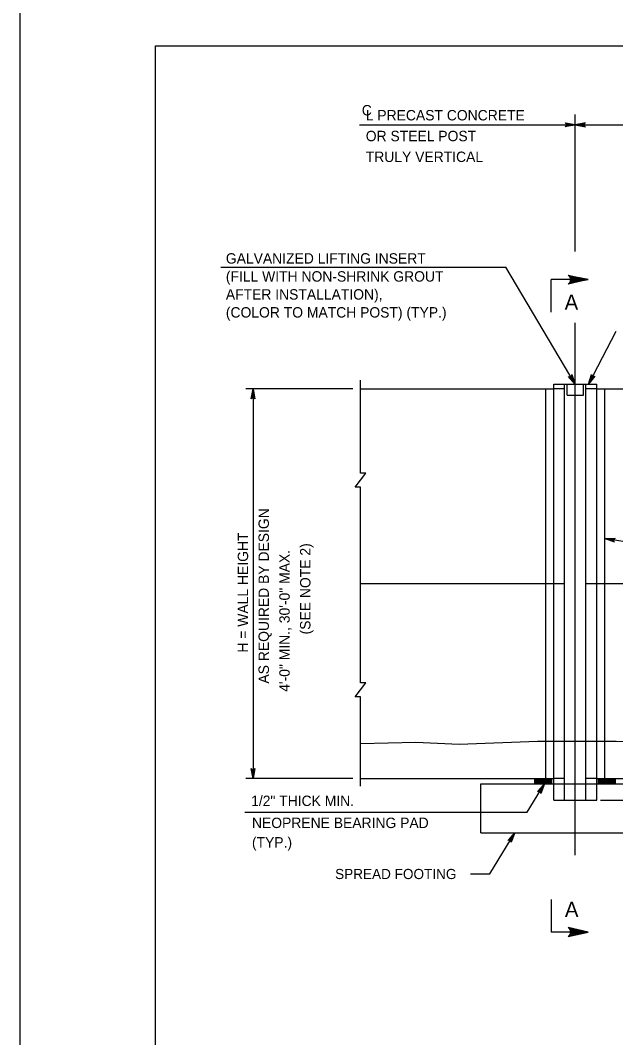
# Model space of a CAD drawing. Extents: x 3761 to 5458, y -616 to 1166.
# Drawn here: x 3761.3 to 3937.4, y 263.6 to 564.2 of the extents above; entities that cross this region are included whole.
import ezdxf

# ---------------------------------------------------------------- set-up
doc = ezdxf.new("R2010")
doc.units = 0
for name, color, linetype in [('1', 7, 'Continuous'), ('2', 7, 'Continuous'), ('PLT-BNDY', 7, 'Continuous')]:
    doc.layers.add(name, color=color, linetype=linetype)

msp = doc.modelspace()

# ---------------------------------------------------------------- linework, layer by layer
at = {"layer": '1'}
for p, q in [((3925.47, 495.93), (3925.47, 536.33)), ((3861.66, 533.3), (4143.42, 533.3)), ((3820.64, 491.27), (3904.95, 491.27)), ((3925.47, 456.66), (3904.95, 491.27)), ((3918.31, 478), (3918.31, 487.65)), ((3929.31, 487.65), (3918.31, 487.65)), ((3925.47, 317.53), (3925.47, 474.78)), ((3937.42, 472.24), (3929.42, 456.66)), ((3861.98, 430.38), (3861.98, 457.89)), ((3859.69, 455.3), (3828, 455.3)), ((3830.16, 455.3), (3830.16, 340.1)), ((3861.98, 455.3), (3919.12, 455.3)), ((3916.72, 340.1), (3916.72, 455.3)), ((3919.12, 338.52), (3919.12, 456.66)), ((3919.12, 456.66), (3931.81, 456.66)), ((3922.29, 455.3), (3919.12, 455.3)), ((3922.29, 333.72), (3922.29, 456.66)), ((3923.07, 453.46), (3923.07, 456.66)), ((3927.87, 453.46), (3927.87, 456.66)), ((3928.64, 333.72), (3928.64, 456.66)), ((3931.81, 455.3), (3928.64, 455.3)), ((3931.81, 338.52), (3931.81, 456.66)), ((3931.81, 455.3), (4072.72, 455.3)), ((3934.21, 340.1), (3934.21, 455.3)), ((3923.07, 453.46), (3927.87, 453.46)), ((3861.98, 368.44), (3861.98, 426.21)), ((4070.32, 388.95), (3934.21, 411.04)), ((3922.29, 397.7), (3861.98, 397.7)), ((4075.89, 397.7), (3928.64, 397.7)), ((3861.98, 337.85), (3861.98, 364.26)), ((3859.69, 340.1), (3828, 340.1)), ((3861.98, 340.1), (3919.12, 340.1)), ((3913.56, 338.52), (3913.56, 340.1)), ((3913.56, 339.92), (3918.55, 339.92)), ((3918.55, 338.52), (3918.55, 340.1)), ((3922.29, 340.1), (3919.12, 340.1)), ((3931.81, 340.1), (3928.64, 340.1)), ((3931.81, 340.1), (3944.01, 340.1)), ((3932.37, 338.52), (3932.37, 340.1)), ((3932.37, 339.92), (3937.37, 339.92)), ((3937.37, 338.52), (3937.37, 340.1)), ((3897.57, 338.52), (3953.36, 338.52)), ((3897.57, 324.12), (3897.57, 338.52)), ((3911.28, 330.21), (3916.34, 338.52)), ((3913.56, 339.72), (3918.55, 339.72)), ((3913.56, 339.52), (3918.55, 339.52)), ((3913.56, 339.32), (3918.55, 339.32)), ((3913.56, 339.12), (3918.55, 339.12)), ((3913.56, 338.92), (3918.55, 338.92)), ((3913.56, 338.72), (3918.55, 338.72)), ((3913.56, 338.52), (3918.55, 338.52)), ((3919.12, 333.72), (3919.12, 338.52)), ((3931.81, 333.72), (3931.81, 338.52)), ((3932.37, 339.72), (3937.37, 339.72)), ((3932.37, 339.52), (3937.37, 339.52)), ((3932.37, 339.32), (3937.37, 339.32)), ((3932.37, 339.12), (3937.37, 339.12)), ((3932.37, 338.92), (3937.37, 338.92)), ((3932.37, 338.72), (3937.37, 338.72)), ((3919.12, 333.72), (3931.81, 333.72)), ((3932.96, 333.72), (3947.1, 333.72)), ((3827.77, 330.21), (3911.28, 330.21)), ((3897.57, 324.12), (3953.36, 324.12)), ((3900.19, 311.96), (3907.59, 324.12)), ((3894.52, 311.96), (3900.19, 311.96)), ((3918.31, 304.39), (3918.31, 294.74)), ((3929.31, 294.74), (3918.31, 294.74))]:
    msp.add_line(p, q, dxfattribs=at)
for points in [[(3925.47, 533.3), (3922.48, 532.74), (3922.6, 532.82), (3922.71, 532.9), (3922.77, 533), (3922.83, 533.1), (3922.85, 533.2), (3922.87, 533.3), (3922.85, 533.4), (3922.83, 533.5), (3922.77, 533.6), (3922.71, 533.7), (3922.6, 533.78), (3922.48, 533.86), (3925.47, 533.3), (3922.6, 533.78), (3922.71, 533.7), (3925.47, 533.3), (3922.77, 533.6), (3922.83, 533.5), (3925.47, 533.3), (3922.85, 533.4), (3922.87, 533.3), (3925.47, 533.3), (3922.85, 533.2), (3922.83, 533.1), (3925.47, 533.3), (3922.77, 533), (3922.71, 532.9), (3925.47, 533.3), (3922.6, 532.82)], [(3925.47, 533.3), (3928.45, 532.74), (3928.33, 532.82), (3928.22, 532.9), (3928.16, 533), (3928.1, 533.1), (3928.08, 533.2), (3928.07, 533.3), (3928.08, 533.4), (3928.1, 533.5), (3928.16, 533.6), (3928.22, 533.7), (3928.33, 533.78), (3928.45, 533.86), (3925.47, 533.3), (3928.33, 533.78), (3928.22, 533.7), (3925.47, 533.3), (3928.16, 533.6), (3928.1, 533.5), (3925.47, 533.3), (3928.08, 533.4), (3928.07, 533.3), (3925.47, 533.3), (3928.08, 533.2), (3928.1, 533.1), (3925.47, 533.3), (3928.16, 533), (3928.22, 532.9), (3925.47, 533.3), (3928.33, 532.82)], [(3929.31, 487.65), (3923.35, 486.23), (3923.58, 486.43), (3923.81, 486.62), (3923.93, 486.86), (3924.04, 487.1), (3924.08, 487.34), (3924.11, 487.58), (3924.07, 487.82), (3924.03, 488.06), (3923.91, 488.3), (3923.79, 488.54), (3923.56, 488.73), (3923.33, 488.92), (3929.31, 487.65), (3923.56, 488.73), (3923.79, 488.54), (3929.31, 487.65), (3923.91, 488.3), (3924.03, 488.06), (3929.31, 487.65), (3924.07, 487.82), (3924.11, 487.58), (3929.31, 487.65), (3924.08, 487.34), (3924.04, 487.1), (3929.31, 487.65), (3923.93, 486.86), (3923.81, 486.62), (3929.31, 487.65), (3923.58, 486.43)], [(3925.47, 456.66), (3923.46, 458.94), (3923.72, 458.82), (3923.95, 458.82), (3924.14, 458.89), (3924.29, 459.02), (3924.41, 459.23), (3924.43, 459.51), (3925.47, 456.66), (3924.41, 459.23), (3924.29, 459.02), (3925.47, 456.66), (3924.14, 458.89), (3923.95, 458.82), (3925.47, 456.66), (3923.72, 458.82)], [(3929.42, 456.66), (3930.28, 459.56), (3930.3, 459.43), (3930.32, 459.29), (3930.38, 459.19), (3930.44, 459.09), (3930.53, 459.03), (3930.61, 458.97), (3930.7, 458.94), (3930.8, 458.91), (3930.92, 458.92), (3931.03, 458.92), (3931.16, 458.99), (3931.28, 459.05), (3929.42, 456.66), (3931.16, 458.99), (3931.03, 458.92), (3929.42, 456.66), (3930.92, 458.92), (3930.8, 458.91), (3929.42, 456.66), (3930.7, 458.94), (3930.61, 458.97), (3929.42, 456.66), (3930.53, 459.03), (3930.44, 459.09), (3929.42, 456.66), (3930.38, 459.19), (3930.32, 459.29), (3929.42, 456.66), (3930.3, 459.43)], [(3830.16, 455.3), (3830.72, 452.32), (3830.64, 452.44), (3830.56, 452.55), (3830.46, 452.61), (3830.36, 452.67), (3830.26, 452.69), (3830.16, 452.7), (3830.06, 452.69), (3829.96, 452.67), (3829.86, 452.61), (3829.76, 452.55), (3829.68, 452.44), (3829.6, 452.32), (3830.16, 455.3), (3829.68, 452.44), (3829.76, 452.55), (3830.16, 455.3), (3829.86, 452.61), (3829.96, 452.67), (3830.16, 455.3), (3830.06, 452.69), (3830.16, 452.7), (3830.16, 455.3), (3830.26, 452.69), (3830.36, 452.67), (3830.16, 455.3), (3830.46, 452.61), (3830.56, 452.55), (3830.16, 455.3), (3830.64, 452.44)], [(3861.98, 426.21), (3860.39, 426.21), (3863.56, 430.38), (3861.98, 430.38)], [(3934.21, 411.04), (3937.25, 411.11), (3936.99, 410.99), (3936.85, 410.82), (3936.78, 410.62), (3936.78, 410.42), (3936.87, 410.2), (3937.07, 410.01), (3934.21, 411.04), (3936.87, 410.2), (3936.78, 410.42), (3934.21, 411.04), (3936.78, 410.62), (3936.85, 410.82), (3934.21, 411.04), (3936.99, 410.99)], [(3861.98, 364.26), (3860.39, 364.26), (3863.56, 368.44), (3861.98, 368.44)], [(3861.98, 350.45), (3878.35, 350.9), (3891.12, 350.32), (3914.31, 351.17), (3937.57, 351.17), (3961.32, 351.07), (3966.64, 351.17), (3982.01, 351.07), (3996.76, 351.17), (4011.56, 350.95), (4046.92, 351.17), (4066.47, 350.64), (4086.26, 348.09), (4094.49, 346.67), (4106.93, 345.35), (4120.71, 343.61), (4143.22, 341.33), (4160.6, 339.19), (4243, 332.75), (4279.86, 332.38)], [(3830.16, 340.1), (3829.6, 343.09), (3829.68, 342.97), (3829.76, 342.86), (3829.86, 342.8), (3829.96, 342.74), (3830.06, 342.72), (3830.16, 342.7), (3830.26, 342.72), (3830.36, 342.74), (3830.46, 342.8), (3830.56, 342.86), (3830.64, 342.97), (3830.72, 343.09), (3830.16, 340.1), (3830.64, 342.97), (3830.56, 342.86), (3830.16, 340.1), (3830.46, 342.8), (3830.36, 342.74), (3830.16, 340.1), (3830.26, 342.72), (3830.16, 342.7), (3830.16, 340.1), (3830.06, 342.72), (3829.96, 342.74), (3830.16, 340.1), (3829.86, 342.8), (3829.76, 342.86), (3830.16, 340.1), (3829.68, 342.97)], [(3916.34, 338.52), (3915.26, 335.68), (3915.25, 335.82), (3915.25, 335.96), (3915.19, 336.06), (3915.14, 336.16), (3915.06, 336.23), (3914.98, 336.3), (3914.89, 336.33), (3914.8, 336.37), (3914.68, 336.37), (3914.56, 336.37), (3914.44, 336.32), (3914.31, 336.26), (3916.34, 338.52), (3914.44, 336.32), (3914.56, 336.37), (3916.34, 338.52), (3914.68, 336.37), (3914.8, 336.37), (3916.34, 338.52), (3914.89, 336.33), (3914.98, 336.3), (3916.34, 338.52), (3915.06, 336.23), (3915.14, 336.16), (3916.34, 338.52), (3915.19, 336.06), (3915.25, 335.96), (3916.34, 338.52), (3915.25, 335.82)], [(3907.59, 324.12), (3906.52, 321.28), (3906.51, 321.42), (3906.5, 321.56), (3906.45, 321.66), (3906.39, 321.76), (3906.32, 321.83), (3906.24, 321.9), (3906.15, 321.93), (3906.05, 321.97), (3905.94, 321.97), (3905.82, 321.97), (3905.69, 321.92), (3905.56, 321.86), (3907.59, 324.12), (3905.69, 321.92), (3905.82, 321.97), (3907.59, 324.12), (3905.94, 321.97), (3906.05, 321.97), (3907.59, 324.12), (3906.15, 321.93), (3906.24, 321.9), (3907.59, 324.12), (3906.32, 321.83), (3906.39, 321.76), (3907.59, 324.12), (3906.45, 321.66), (3906.5, 321.56), (3907.59, 324.12), (3906.51, 321.42)], [(3929.31, 294.74), (3923.35, 296.15), (3923.58, 295.96), (3923.81, 295.77), (3923.93, 295.53), (3924.04, 295.28), (3924.08, 295.04), (3924.11, 294.8), (3924.07, 294.56), (3924.03, 294.32), (3923.91, 294.09), (3923.79, 293.85), (3923.56, 293.66), (3923.33, 293.47), (3929.31, 294.74), (3923.56, 293.66), (3923.79, 293.85), (3929.31, 294.74), (3923.91, 294.09), (3924.03, 294.32), (3929.31, 294.74), (3924.07, 294.56), (3924.11, 294.8), (3929.31, 294.74), (3924.08, 295.04), (3924.04, 295.28), (3929.31, 294.74), (3923.93, 295.53), (3923.81, 295.77), (3929.31, 294.74), (3923.58, 295.96)]]:
    msp.add_lwpolyline(points, dxfattribs=at)
at = {"layer": '2'}
for p, q in [((3801.34, -7.31), (3801.34, 556.69)), ((3801.34, 556.69), (4587.34, 556.69))]:
    msp.add_line(p, q, dxfattribs=at)
at = {"layer": 'PLT-BNDY'}
msp.add_lwpolyline([(3761.34, 571.69), (4602.34, 571.69), (4602.34, -22.31), (3761.34, -22.31)], close=True, dxfattribs=at)

# ---------------------------------------------------------------- texts
at = {"layer": '1'}
for s, height, p in [('C', 3.07, (3862.33, 536.09)), ('L PRECAST CONCRETE ', 3.072, (3863.51, 534.62)), ('OR STEEL POST', 3.072, (3863.51, 528.47)), ('TRULY VERTICAL', 3.072, (3863.51, 522.33)), ('GALVANIZED LIFTING INSERT', 3.072, (3822.13, 492.3)), ('(FILL WITH NON-SHRINK GROUT', 3.072, (3822.13, 486.98)), ('AFTER INSTALLATION),', 3.072, (3822.13, 481.67)), ('A', 4.48, (3922.33, 478.67)), ('(COLOR TO MATCH POST) (TYP.)', 3.072, (3822.13, 476.36)), ('1/2" THICK MIN.', 3.072, (3829.6, 332.01)), ('NEOPRENE BEARING PAD', 3.072, (3829.85, 325.5)), ('(TYP.)', 3.072, (3829.85, 319.74)), ('SPREAD FOOTING', 3, (3854.44, 310.42)), ('A', 4.48, (3922.41, 299.24))]:
    msp.add_text(s, height=height, dxfattribs=at).set_placement(p)
for s, p in [('AS REQUIRED BY DESIGN', (3834.86, 368.19)), ('H = WALL HEIGHT', (3828.72, 377.34)), ('(SEE NOTE 2)', (3847.15, 382.72)), ('4\'-0" MIN., 30\'-0" MAX.', (3841.01, 365.76))]:
    msp.add_text(s, height=3.072, rotation=90, dxfattribs=at).set_placement(p)

doc.saveas('drawing.dxf')
